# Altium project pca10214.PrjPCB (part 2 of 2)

## Sheet pca10214_sheet7_connectors.SchDoc: =BoardTitle+' - Connectors'
size A3; Organization: Nordic Semiconductor; DocumentNumber: 7; Revision: 0.3.1; SheetNumber: 7; SheetTotal: 8; Author: KJP; CompanyName: Nordic Semiconductor; DrawnBy: KJP; DocumentSize: A4
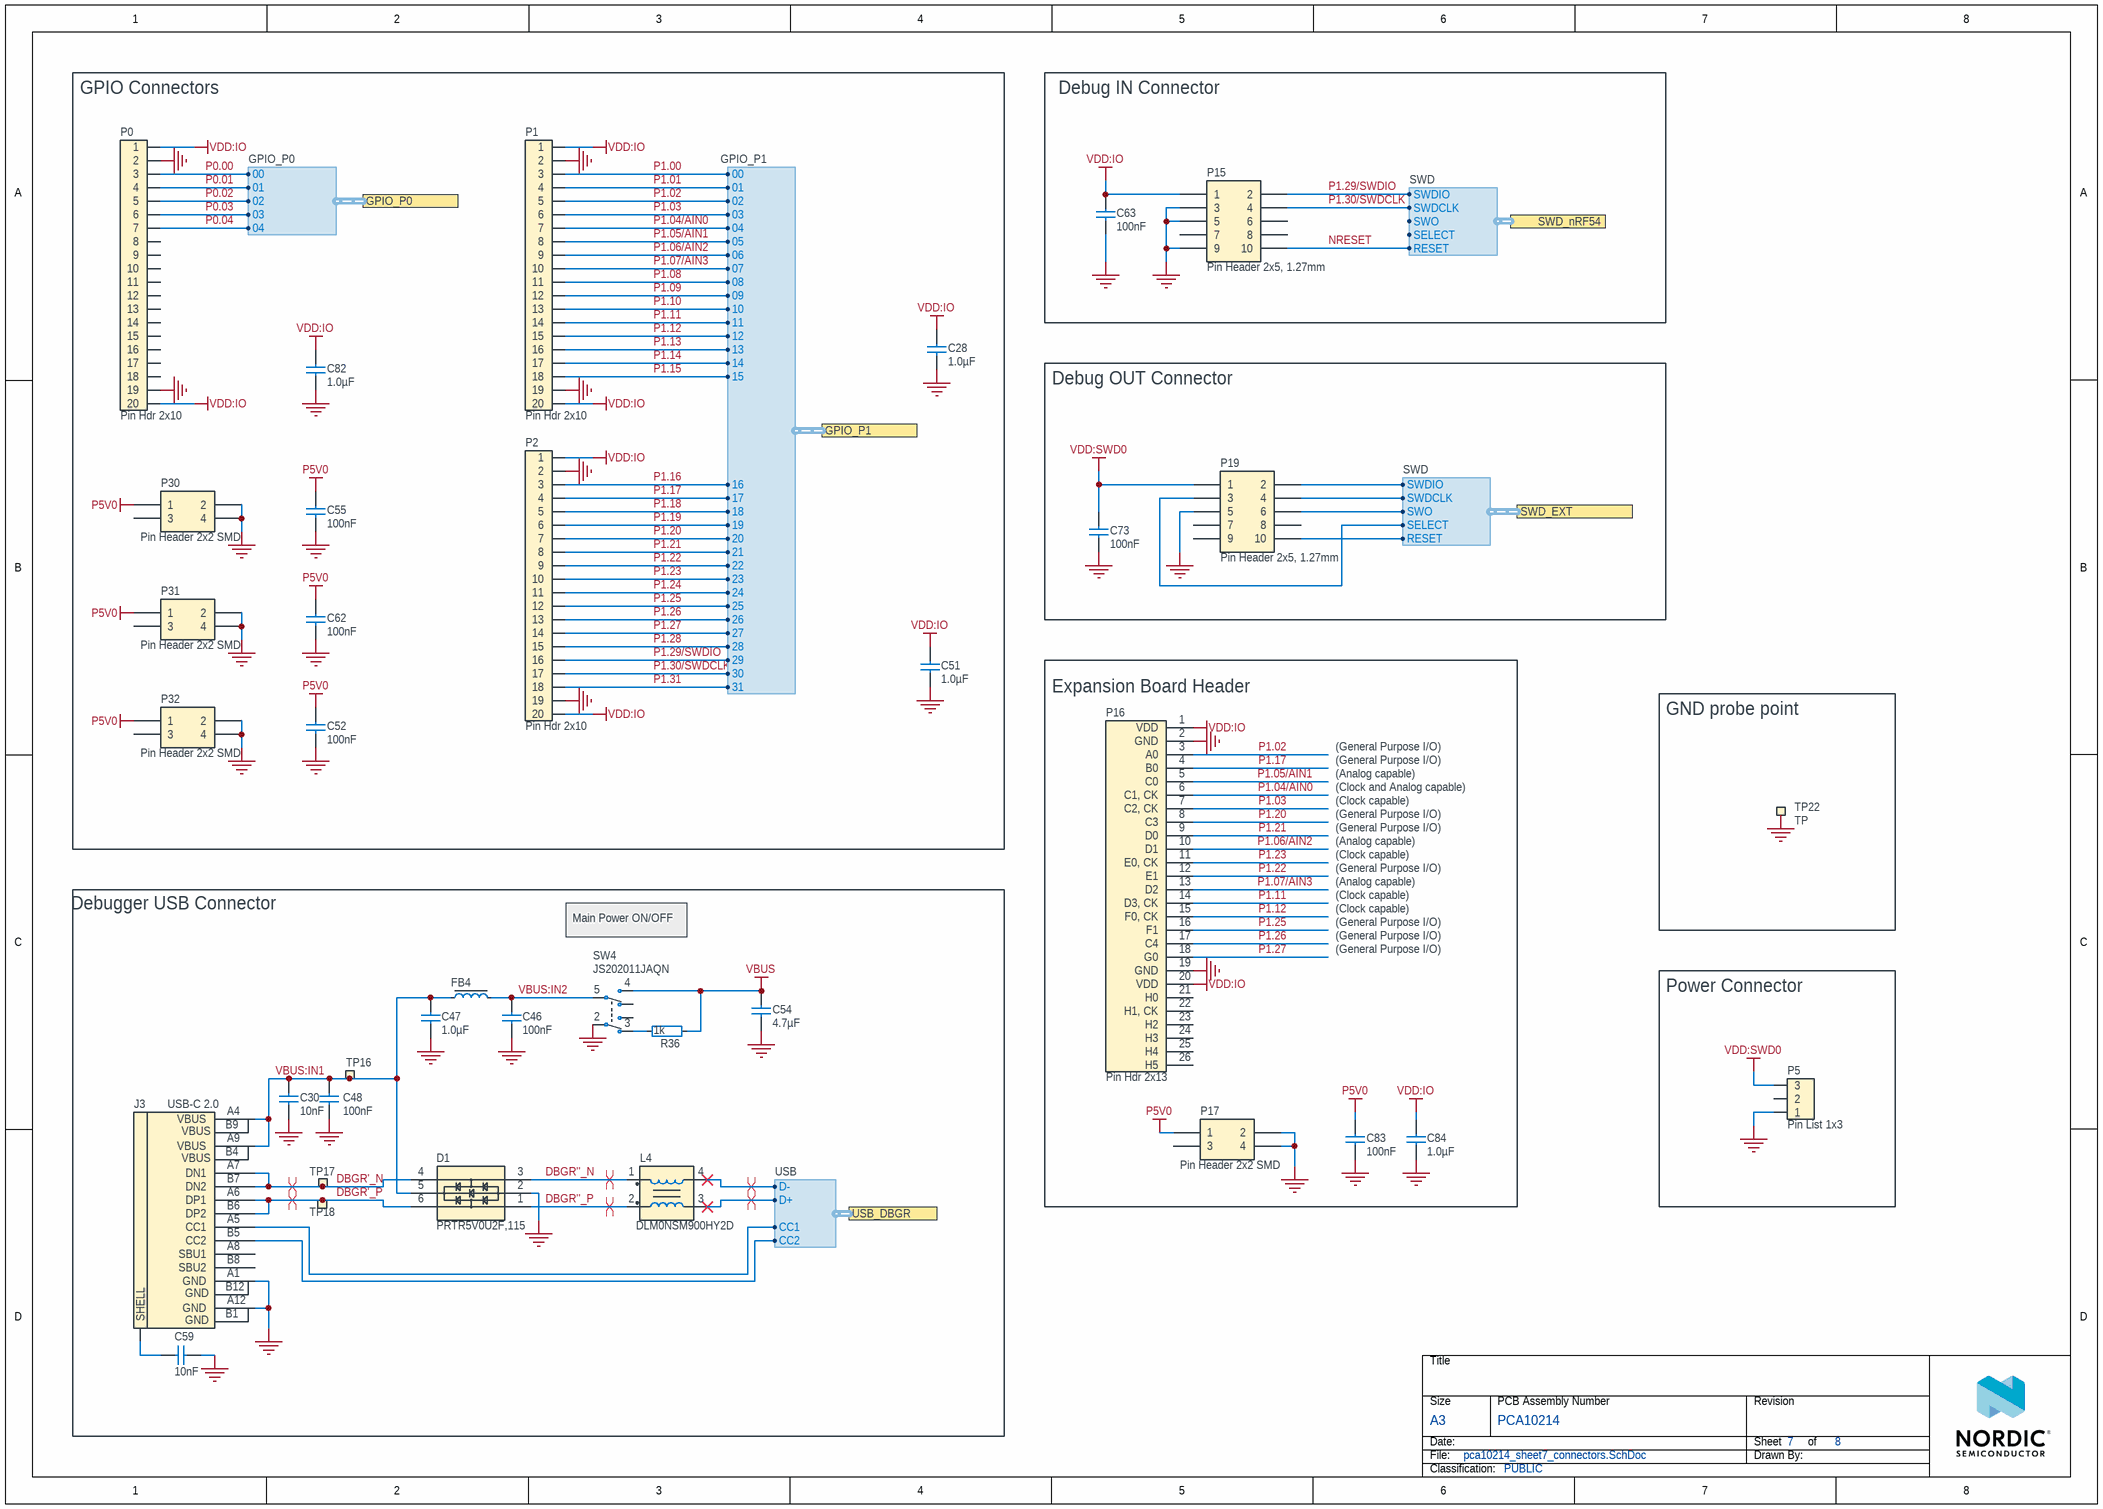
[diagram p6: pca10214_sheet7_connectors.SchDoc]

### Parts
C28  1.0µF  [CAPC1005X04L]
C30  10nF  [CAPC0603X03L_C]
C46  100nF  [CAPC0603X03L_C]
C47  1.0µF  [CAPC1005X04L]
C48  100nF  [CAPC0603X03L_C]
C51  1.0µF  [CAPC1005X04L]
C52  100nF  [CAPC0603X03L_C]
C54  4.7µF  [CAPC1608X06L]
C55  100nF  [CAPC0603X03L_C]
C59  10nF  [CAPC1608X06L]
C62  100nF  [CAPC0603X03L_C]
C63  100nF  [CAPC0603X03L_C]
C73  100nF  [CAPC0603X03L_C]
C82  1.0µF  [CAPC1005X04L]
C83  100nF  [CAPC0603X03L_C]
C84  1.0µF  [CAPC1005X04L]
D1  PRTR5V0U2F,115  [SON50P100X50-6N]
FB4  120R/0.55A  [INDC1005X04L]  (value not drawn)
J3  USB-C 2.0  [SD-80259-001]
L4  DLM0NSM900HY2D  [CMC0806X05N]
P0  Pin Hdr 2x10  [HDR_2x10-SMD]
P1  Pin Hdr 2x10  [HDR_2x10-SMD]
P2  Pin Hdr 2x10  [HDR_2x10-SMD]
P5  Pin List 1x3  [LIST_1x3_SMD]
P15  Pin Header 2x5, 1.27mm  [HDR_2x5-SMD-1.27mm-K]
P16  Pin Hdr 2x13  [HDR_2x13-SMD]
P17  Pin Header 2x2 SMD  [HDR_2x2-SMD]
P19  Pin Header 2x5, 1.27mm  [HDR_2x5-SMD-1.27mm-K]
P30  Pin Header 2x2 SMD  [HDR_2x2-SMD]
P31  Pin Header 2x2 SMD  [HDR_2x2-SMD]
P32  Pin Header 2x2 SMD  [HDR_2x2-SMD]
R36  1k  [RESC0603X03L_C]
SW4  Manufacturer Part Number: JS202011JAQN  [JS102011JAQN]  (hidden comment: Switch)
TP16  Ø1.5mm,SMD  [TP_SMD_D1.5mm]  (value not drawn)  (no BOM)
TP17  Ø1.5mm,SMD  [TP_SMD_D1.5mm]  (value not drawn)  (no BOM)
TP18  Ø1.5mm,SMD  [TP_SMD_D1.5mm]  (value not drawn)  (no BOM)
TP22  TP  [S1751]

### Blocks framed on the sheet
GPIO Connectors: C28 C51 C52 C55 C62 C82 P0-P2 P30-P32
Debug IN Connector: C63 P15
Debug OUT Connector: C73 P19
Expansion Board Header: C83 C84 P16 P17
GND probe point: TP22
Debugger USB Connector: C30 C46-C48 C54 C59 D1 FB4 J3 L4 R36 SW4 TP16-TP18
Power Connector: P5

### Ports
GPIO_P0 (harness GPIO_P0), GPIO_P1 (harness GPIO_P1), SWD_EXT (harness SWD), SWD_nRF54 (harness SWD), USB_DBGR (harness USB)

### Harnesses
USB: D+, D-, CC1, CC2
SWD: SWDIO, SWDCLK, SWO, RESET, SELECT
GPIO_P0: 02, 03, 04, 00, 01
GPIO_P1: 02, 03, 04, 00, 01, 05, 06, 07, 08, 09, 10, 11, 12, 13, 14, 15, 16, 17, 18, 19, 20, 21, 22, 23, 24, 25, 26, 27, 28, 29, 30, 31

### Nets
GND: C28.1 C30.2 C46.1 C47.1 C48.1 C51.1 C52.1 C54.2 C55.1 C59.2 C62.1 C63.1 C73.1 C82.1 C83.1 C84.1 D1.2(GND) J3.A1(GND) J3.A12(GND) P0.2 P0.19 P1.2 P1.19 P2.2 P2.19 P5.1 P15.3 P15.5 P15.9 P16.2(GND) P16.19(GND) P17.2 P17.4 P19.5 P30.2 P30.4 P31.2 P31.4 P32.2 P32.4 SW4.2(COM-1) TP22.1
P5V0: C52.2 C55.2 C62.2 C83.2 P17.1 P30.1 P31.1 P32.1
VBUS: C54.1 R36.2 SW4.4(N.O-2)
VDD:IO: C28.2 C51.2 C63.2 C82.2 C84.2 P0.1 P0.20 P1.1 P1.20 P2.1 P2.20 P15.1 P16.1(VDD) P16.20(VDD)
VDD:SWD0: C73.2 P5.3 P19.1
DBGR''_N: D1.3(IO2) L4.1
DBGR''_P: D1.1(IO1) L4.2
DBGR'_N: D1.4(IO2) J3.A7(DN1) J3.B7(DN2) TP17.1
DBGR'_P: D1.6(IO1) J3.A6(DP1) J3.B6(DP2) TP18.1
DBGR_N: L4.4 ; port USB_DBGR.D-
DBGR_P: L4.3 ; port USB_DBGR.D+
NRESET: P15.10 ; port SWD_nRF54.RESET
P0.00: P0.3 ; port GPIO_P0.00
P0.01: P0.4 ; port GPIO_P0.01
P0.02: P0.5 ; port GPIO_P0.02
P0.03: P0.6 ; port GPIO_P0.03
P0.04: P0.7 ; port GPIO_P0.04
P1.00: P1.3 ; port GPIO_P1.00
P1.01: P1.4 ; port GPIO_P1.01
P1.02: P1.5 P16.3(A0) ; port GPIO_P1.02
P1.03: P1.6 P16.7(C2,_CK) ; port GPIO_P1.03
P1.04/AIN0: P1.7 P16.6(C1,_CK) ; port GPIO_P1.04
P1.05/AIN1: P1.8 P16.5(C0) ; port GPIO_P1.05
P1.06/AIN2: P1.9 P16.10(D1) ; port GPIO_P1.06
P1.07/AIN3: P1.10 P16.13(D2) ; port GPIO_P1.07
P1.08: P1.11 ; port GPIO_P1.08
P1.09: P1.12 ; port GPIO_P1.09
P1.10: P1.13 ; port GPIO_P1.10
P1.11: P1.14 P16.14(D3,_CK) ; port GPIO_P1.11
P1.12: P1.15 P16.15(F0,_CK) ; port GPIO_P1.12
P1.13: P1.16 ; port GPIO_P1.13
P1.14: P1.17 ; port GPIO_P1.14
P1.15: P1.18 ; port GPIO_P1.15
P1.16: P2.3 ; port GPIO_P1.16
P1.17: P2.4 P16.4(B0) ; port GPIO_P1.17
P1.18: P2.5 ; port GPIO_P1.18
P1.19: P2.6 ; port GPIO_P1.19
P1.20: P2.7 P16.8(C3) ; port GPIO_P1.20
P1.21: P2.8 P16.9(D0) ; port GPIO_P1.21
P1.22: P2.9 P16.12(E1) ; port GPIO_P1.22
P1.23: P2.10 P16.11(E0,_CK) ; port GPIO_P1.23
P1.24: P2.11 ; port GPIO_P1.24
P1.25: P2.12 P16.16(F1) ; port GPIO_P1.25
P1.26: P2.13 P16.17(C4) ; port GPIO_P1.26
P1.27: P2.14 P16.18(G0) ; port GPIO_P1.27
P1.28: P2.15 ; port GPIO_P1.28
P1.29/SWDIO: P2.16 P15.2 ; port SWD_nRF54.SWDIO, port GPIO_P1.29
P1.30/SWDCLK: P2.17 P15.4 ; port SWD_nRF54.SWDCLK, port GPIO_P1.30
P1.31: P2.18 ; port GPIO_P1.31
SWD0_CLK_EXT: P19.4 ; port SWD_EXT.SWDCLK
SWD0_IO_EXT: P19.2 ; port SWD_EXT.SWDIO
SWD0_RESET_EXT: P19.10 ; port SWD_EXT.RESET
SWD0_SEL: P19.3 ; port SWD_EXT.SELECT
SWD0_SWO_EXT: P19.6 ; port SWD_EXT.SWO
VBUS:IN1: C30.1 C47.2 C48.2 D1.5(VCC) FB4.1 J3.A4(VBUS) J3.A9(VBUS) TP16.1
VBUS:IN2: C46.2 FB4.2 SW4.5(COM-2)
NetC59_1: C59.1 J3.SHLD(SHELL)
NetJ3_A5: J3.A5(CC1) ; port USB_DBGR.CC1
NetJ3_B5: J3.B5(CC2) ; port USB_DBGR.CC2
NetR36_1: R36.1 SW4.3(N.C-1)

Not connected (* = marked no-connect by the designer): J3 A8(SBU1) B8(SBU2); P0 8 9 10 11 12 13 14 15 16 17 18; P5 2; P15 6 7 8; P16 21(H0) 22(H1,_CK) 23(H2) 24(H3) 25(H4) 26(H5); P17 3; P19 7 8 9; P30 3; P31 3; P32 3; SW4 1(N.O-1) 6(N.C-2)

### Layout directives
differential pair; differential pair class DBGR; net class DBGR_USB: DBGR''_N, DBGR''_P, DBGR'_N, DBGR'_P, DBGR_N, DBGR_P

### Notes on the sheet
- (General Purpose I/O)
- (Analog capable)
- (Clock capable)
- (Clock and Analog capable)
- Main Power ON/OFF

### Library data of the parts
C28 C51 C82 C84 = C0402-1µ0-6.3V-X5R-10%: Capacitor, X5R, ±10%, 6.3V; Manufacturer: N.A.; Part number Norautron: 26207137; Part number NEMS: 100200498; Pad Count: 2; Component Status: Active
C30 = C0201-10n: Capacitor, X7R, ±10%; Manufacturer: N.A.; Part number IPS: 00000003480; Part number Norautron: 26621779; Part number NEMS: 100200067; Note: 10V; Pad Count: 2; Component Status: Active
C46 C48 C52 C55 C62 C63 C73 C83 = C0201-100n: Capacitor, X5R, ±10%; Manufacturer: N.A.; Part number IPS: 00000001248, 00000002505; Part number Norautron: 262071862; Part number NEMS: 100200078; Note: 16V; Pad Count: 2; Component Status: Active
C47 = C0402-1µ0-16V-X5R: Capacitor, Ceramic, X5R, ±10%, 16V; Manufacturer: Murata; Manufacturer Part Number: GRT155R61C105KE01D; Part number NEMS: 100200452; Component Status: Active; Pad Count: 2; Artikkelnr Noca: N.A.
C54 = C0603-4µ7-10V-X7S: Capacitor, X7S, ±10%, 10V; Manufacturer: N.A.; Part number IPS: 00000001779; Part number NEMS: 100200351; Pad Count: 2; Artikkelnr Noca: 20030013; Component Status: Active
C59 = C0603-10n-100V-X7R: Capacitor, X7R, ±10%, 100V; Manufacturer: Murata; Manufacturer Part Number: GCM188R72A103KA37D; Part number NEMS: 100200349; Component Status: Active; Pad Count: 2; Artikkelnr Noca: N.A.
D1 = PRTR5V0U2F,115: TVS DIODE 5.5VWM 6XSON; Manufacturer: Nexperia; Part number NEMS: 101300202; Component Status: Active; Pad Count: 6; Note: N.A.
FB4 = FB0402-120R@100M-500mA: Ferrite Bead, 120 Ohm @ 100MHz, 500mA, 250 mOhm Max; Manufacturer: Murata; Manufacturer Part Number: BLM15AG121SN1D; Part number IPS: 00000009954; Part number Norautron: 265230631; Part number NEMS: 100300099; Note: Chip EMIFIL Inductor Type Chip Ferrite Bead; Artikkelnr Noca: 33029317; Pad Count: 2; Component Status: Active
J3 = SD-80259-1021: USB-C Receptacle, 16 Pin, USB 2.0; Manufacturer: Bellweather Electronic Corp.; Part number NEMS: 100500830; Component Status: Active; Pad Count: 16; Note: N.A.; System: Connector
L4 = DLM0NSM900HY2D: 2 Line Common Mode Choke, 90Ohm @ 100MHz, Imax=100mA, DCR=4Ohm, VDC=5V,  -40°C ~ 85°C; Manufacturer: Murata Electronics; Part number NEMS: 100300513; Component Status: Active; Pad Count: 4; Note: N.A.
P0-P2 = Pin Header 2x10 SMD, 2.54mm: Pin Header 2x10, 2.54mm (100mil) SMD; Manufacturer: WCON; Manufacturer Part Number: 1125-1210S0M116CR09; Part number NEMS: 100500738; Pad Count: 20; Artikkelnr Noca: N.A.; Component Status: Active; System: Connector
P5 = Pin List 1x3 SMD: Pin List 1x3, 2.54mm (100mil), SMD; Manufacturer: WCON; Manufacturer Part Number: 1125-1103S0M116CR04; Part number Norautron: 26470016; Part number NEMS: 100500306; Note: N.A.; Pad Count: 3; Component Status: Active; System: Connector
P15 P19 = Pin Header 2x5 SMD, 1.27mm, KS: Pin Header 2x5, 1.27mm (50mil), SMD, Keying Shroud; Manufacturer: WCON; Manufacturer Part Number: 3132-10MS0BK00R5; Part number NEMS: 100500261; Note: (Replaced 3132-10MS0BK00R1); Artikkelnr Noca: N.A.; Pad Count: 10; Component Status: Active; System: Connector
P16 = Pin Header 2x13 SMD, 2.54mm: Pin Header 2x13, 2.54mm (100mil) SMD; Manufacturer: WCON; Manufacturer Part Number: 1125-1213S0M116CR09; Part number NEMS: 100500908; Component Status: Active; Pad Count: 26; Artikkelnr Noca: N.A.; System: Connector
P17 P30-P32 = Pin Header 2x2 SMD: Pin Header 2x2, SMD, 2.54mm (100mil); Manufacturer: WCON; Manufacturer Part Number: 1125-1202S0M116CR03; Part number NEMS: 100500770; Component Status: Active; Pad Count: 4; Note: N.A.; System: Connector
R36 = R0201-1k0: Resistor, ±1%, 0.05W; Manufacturer: N.A.; Part number IPS: 00000005786; Part number NEMS: 100100043; Component Status: Active; Pad Count: 2; Note: Chip Res 1%
SW4 = Switch-Slide-RA-J-Lead-DPDT-8.5x3.5mm_C&K: SMD slide Switch (ON-ON); Manufacturer: C&K; Part number IPS: 00000007811; Part number NEMS: 101500037; Component Status: Active; Pad Count: 6; Note: N.A.
TP16-TP18 = TP_SMD_Ø1.5MM: 1.5mm circular SMD testpad; Manufacturer: Nordic Semiconductor; Manufacturer Part Number: N.A.; Part number NEMS: 100500477; Pad Count: 1; Component Status: Active
TP22 = TP - S1751-46R: PC TEST POINT TIN SMD L; Manufacturer: Harwin; Part number NEMS: 100500525; Component Status: Active; Pad Count: 1; Note: N.A.

## Sheet pca10214_sheet8_mechanical.SchDoc: =BoardTitle+' - Mechanical'
size A4; Organization: Nordic Semiconductor; DocumentNumber: 89; Revision: 0.3.1; SheetNumber: 8; SheetTotal: 8; Author: KJP; CompanyName: Nordic Semiconductor; DrawnBy: KJP; DocumentSize: A4
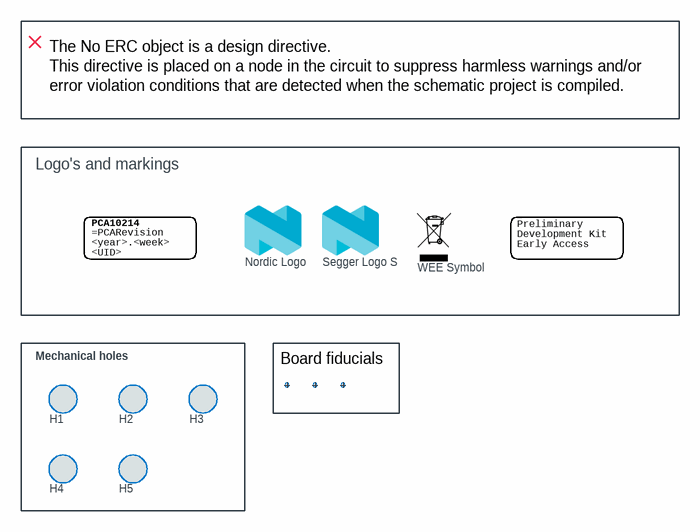
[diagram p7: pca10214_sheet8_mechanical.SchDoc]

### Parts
Fid1  Fiducial mark  [Fiducial]  (value not drawn)
Fid2  Fiducial mark  [Fiducial]  (value not drawn)
Fid3  Fiducial mark  [Fiducial]  (value not drawn)
H1  MountingHole_NPTH  [MountingHole_3.2_M3]  (value not drawn)  (no BOM)
H2  MountingHole_NPTH  [MountingHole_3.2_M3]  (value not drawn)  (no BOM)
H3  MountingHole_NPTH  [MountingHole_3.2_M3]  (value not drawn)  (no BOM)
H4  MountingHole_NPTH  [MountingHole_3.2_M3]  (value not drawn)  (no BOM)
H5  MountingHole_NPTH  [MountingHole_3.2_M3]  (value not drawn)  (no BOM)
LABEL1  12x12mm  [LabelSilk_12x12]  (value not drawn)
LABEL2  20x40mm  [LabelSilk_20x40]  (value not drawn)
LOGO1  Nordic Logo  [NORDIC_LOGO_LYING]  (no BOM)
LOGO2  Segger Logo S  [SEGGER_LOGO_S]  (no BOM)
LOGO3  WEE Symbol  [WEEE_3x4.5mm]  (no BOM)

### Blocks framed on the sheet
Logo's and markings: LABEL1 LABEL2 LOGO1-LOGO3
Mechanical holes: H1-H5

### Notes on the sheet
- The No ERC object is a design directive.
  This directive is placed on a node in the circuit to suppress harmless warnings and/or error violation conditions that are detected when the schematic project is compiled.
- Board fiducials

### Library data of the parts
Fid1-Fid3 = Fid-Mark: Manufacturer: N.A.; Part number NEMS: 100500073; Value: N.A.; Pad Count: 1; Component Status: Active; System: Connector
H1-H5 = MountingHole_3.2_M3: Mounting hole, 3.2mm, M3, no annular; Manufacturer: N.A.; Part number NEMS: 101200008; Rule: UNIONINDEX=0¦RULEKIND=Clearance¦NETSCOPE=DifferentNets¦LAYERKIND=SameLayer¦NAME=Schematic Clearance Constraint¦GAP=10mil¦GENERICCLEARANCE=10mil¦IGNOREPADTOPADCLEARANCEINFOOTPRINT=TRUE¦OBJECTCLEARANCES=ClearanceObj_Arc-ClearanceObj_Hole:0;ClearanceObj_Track-ClearanceObj_Hole:0;ClearanceObj_SMDPad-ClearanceObj_Hole:0;ClearanceObj_THPad-ClearanceObj_Hole:0;ClearanceObj_Via-ClearanceObj_Hole:0;ClearanceObj_Fill-ClearanceObj_Hole:0;ClearanceObj_Poly-ClearanceObj_Hole:0;ClearanceObj_Region-ClearanceObj_Hole:0;ClearanceObj_Text-ClearanceObj_Hole:0¦UNIT=Metric; Rule: UNIONINDEX=0¦RULEKIND=RoutingVias¦NETSCOPE=AnyNet¦LAYERKIND=SameLayer¦NAME=Schematic Routing Via Style¦HOLEWIDTH=0mil¦WIDTH=0mil¦VIASTYLE=Through Hole¦MINHOLEWIDTH=0mil¦MINWIDTH=0mil¦MAXHOLEWIDTH=78.7402mil¦MAXWIDTH=78.7402mil¦UNIT=Metric; Component Status: Active; Pad Count: 0
LABEL1 = Label_12x12: PCA version label, stick-on, 12x12mm; Manufacturer: Ellco Etikett; Manufacturer Part Number: A33512‐01; Part number NEMS: 101200028; Component Status: Active; Pad Count: 0; Note: N.A.
LABEL2 = Label_20x40: Early Access Label; Manufacturer: NA; Part number NEMS: 101200035; Component Status: Active; Pad Count: 0; Note: N.A.
LOGO1 = Nordic Logo lying: Manufacturer: N.A.; Part number NEMS: 101100001; Component Status: Active; Pad Count: 0
LOGO2 = Segger Logo S: Segger logo, small size; Manufacturer: N.A.; Part number NEMS: 101100004; Component Status: Active; Pad Count: 0
LOGO3 = WEEE Symbol 3x4.5mm: WEEE Directive symbol; Manufacturer: N.A.; Part number NEMS: 101100006; Component Status: Active; Pad Count: 0

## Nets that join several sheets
GND: pca10214_sheet2_nRF54LS05 (21 pins), pca10214_sheet3_debugger (33 pins), pca10214_sheet4_level_shifters (22 pins), pca10214_sheet5_misc (14 pins), pca10214_sheet6_power_supply (26 pins), pca10214_sheet7_connectors (42 pins)
P5V0: pca10214_sheet3_debugger (R40.2), pca10214_sheet6_power_supply (13 pins), pca10214_sheet7_connectors (8 pins)
VBUS: pca10214_sheet3_debugger (J4.5 R5.2), pca10214_sheet6_power_supply (C23.2 TP8.1 U10.21), pca10214_sheet7_connectors (C54.1 R36.2 SW4.4)
VDD:DBGR: pca10214_sheet3_debugger (29 pins), pca10214_sheet4_level_shifters (10 pins), pca10214_sheet6_power_supply (C29.1 U10.12)
VDD:IO: pca10214_sheet3_debugger (R41.2), pca10214_sheet4_level_shifters (7 pins), pca10214_sheet6_power_supply (R9.2 R37.2 TP11.1), pca10214_sheet7_connectors (14 pins)
VDD:nRF: pca10214_sheet2_nRF54LS05 (5 pins), pca10214_sheet4_level_shifters (R28.1), pca10214_sheet6_power_supply (P6.2 R24.1 R43.1)
VDD:SWD0: pca10214_sheet4_level_shifters (C14.1 R18.2 U7.11), pca10214_sheet7_connectors (C73.2 P5.3 P19.1)
DBGR_BUTTON: pca10214_sheet1_connections (SB2.2), pca10214_sheet3_debugger (U2.AL27)
DBGR_N: pca10214_sheet3_debugger (U2.B4), pca10214_sheet7_connectors (L4.4)
DBGR_P: pca10214_sheet3_debugger (U2.B2), pca10214_sheet7_connectors (L4.3)
LED_PWR_CTRL: pca10214_sheet3_debugger (U2.A17), pca10214_sheet6_power_supply (U10.8)
NetC64_2: pca10214_sheet5_misc (5 pins), pca10214_sheet6_power_supply (U10.31)
NetJ3_A5: pca10214_sheet6_power_supply (U10.23), pca10214_sheet7_connectors (J3.A5)
NetJ3_B5: pca10214_sheet6_power_supply (U10.24), pca10214_sheet7_connectors (J3.B5)
NetSB1_2: pca10214_sheet1_connections (SB1.2 SB2.1), pca10214_sheet5_misc (SW1.2)
NRESET: pca10214_sheet1_connections (SB1.1), pca10214_sheet2_nRF54LS05 (P3.1 P4.3 R1.2), pca10214_sheet4_level_shifters (U6.9), pca10214_sheet7_connectors (P15.10)
P0.00: pca10214_sheet2_nRF54LS05 (U1.23), pca10214_sheet5_misc (Q2.2 R10.1), pca10214_sheet7_connectors (P0.3)
P0.01: pca10214_sheet2_nRF54LS05 (U1.24), pca10214_sheet5_misc (Q3.2 R11.1), pca10214_sheet7_connectors (P0.4)
P0.02: pca10214_sheet2_nRF54LS05 (U1.27), pca10214_sheet5_misc (Q2.5 R12.1), pca10214_sheet7_connectors (P0.5)
P0.03: pca10214_sheet2_nRF54LS05 (U1.28), pca10214_sheet5_misc (Q3.5 R27.1), pca10214_sheet7_connectors (P0.6)
P0.04: pca10214_sheet2_nRF54LS05 (U1.29), pca10214_sheet5_misc (SW6.2), pca10214_sheet7_connectors (P0.7)
P1.00: pca10214_sheet2_nRF54LS05 (SB5.2), pca10214_sheet7_connectors (P1.3)
P1.01: pca10214_sheet2_nRF54LS05 (SB6.2), pca10214_sheet7_connectors (P1.4)
P1.02: pca10214_sheet2_nRF54LS05 (U1.3), pca10214_sheet7_connectors (P1.5 P16.3)
P1.03: pca10214_sheet2_nRF54LS05 (U1.4), pca10214_sheet7_connectors (P1.6 P16.7)
P1.04/AIN0: pca10214_sheet2_nRF54LS05 (U1.5), pca10214_sheet4_level_shifters (U5.6), pca10214_sheet7_connectors (P1.7 P16.6)
P1.05/AIN1: pca10214_sheet2_nRF54LS05 (U1.6), pca10214_sheet4_level_shifters (U5.3), pca10214_sheet7_connectors (P1.8 P16.5)
P1.06/AIN2: pca10214_sheet2_nRF54LS05 (U1.7), pca10214_sheet4_level_shifters (U5.13), pca10214_sheet7_connectors (P1.9 P16.10)
P1.07/AIN3: pca10214_sheet2_nRF54LS05 (U1.8), pca10214_sheet4_level_shifters (U5.9), pca10214_sheet7_connectors (P1.10 P16.13)
P1.08: pca10214_sheet2_nRF54LS05 (C41.2 U1.9), pca10214_sheet5_misc (SW5.2), pca10214_sheet7_connectors (P1.11)
P1.09: pca10214_sheet2_nRF54LS05 (U1.37), pca10214_sheet5_misc (SW3.2), pca10214_sheet7_connectors (P1.12)
P1.10: pca10214_sheet2_nRF54LS05 (U1.38), pca10214_sheet4_level_shifters (U4.6), pca10214_sheet7_connectors (P1.13)
P1.11: pca10214_sheet2_nRF54LS05 (U1.39), pca10214_sheet7_connectors (P1.14 P16.14)
P1.12: pca10214_sheet2_nRF54LS05 (U1.40), pca10214_sheet7_connectors (P1.15 P16.15)
P1.13: pca10214_sheet2_nRF54LS05 (U1.41), pca10214_sheet5_misc (SW2.2), pca10214_sheet7_connectors (P1.16)
P1.14: pca10214_sheet2_nRF54LS05 (U1.42), pca10214_sheet4_level_shifters (U4.3), pca10214_sheet7_connectors (P1.17)
P1.15: pca10214_sheet2_nRF54LS05 (U1.48), pca10214_sheet4_level_shifters (U4.13), pca10214_sheet7_connectors (P1.18)
P1.16: pca10214_sheet2_nRF54LS05 (U1.10), pca10214_sheet4_level_shifters (U4.9), pca10214_sheet7_connectors (P2.3)
P1.17: pca10214_sheet2_nRF54LS05 (U1.11), pca10214_sheet7_connectors (P2.4 P16.4)
P1.18: pca10214_sheet2_nRF54LS05 (U1.12), pca10214_sheet7_connectors (P2.5)
P1.19: pca10214_sheet2_nRF54LS05 (U1.13), pca10214_sheet7_connectors (P2.6)
P1.20: pca10214_sheet2_nRF54LS05 (U1.14), pca10214_sheet7_connectors (P2.7 P16.8)
P1.21: pca10214_sheet2_nRF54LS05 (U1.15), pca10214_sheet7_connectors (P2.8 P16.9)
P1.22: pca10214_sheet2_nRF54LS05 (U1.16), pca10214_sheet7_connectors (P2.9 P16.12)
P1.23: pca10214_sheet2_nRF54LS05 (U1.17), pca10214_sheet7_connectors (P2.10 P16.11)
P1.24: pca10214_sheet2_nRF54LS05 (U1.18), pca10214_sheet7_connectors (P2.11)
P1.25: pca10214_sheet2_nRF54LS05 (U1.19), pca10214_sheet7_connectors (P2.12 P16.16)
P1.26: pca10214_sheet2_nRF54LS05 (U1.20), pca10214_sheet7_connectors (P2.13 P16.17)
P1.27: pca10214_sheet2_nRF54LS05 (U1.21), pca10214_sheet7_connectors (P2.14 P16.18)
P1.28: pca10214_sheet2_nRF54LS05 (U1.22), pca10214_sheet7_connectors (P2.15)
P1.29/SWDIO: pca10214_sheet2_nRF54LS05 (U1.25), pca10214_sheet4_level_shifters (U6.6), pca10214_sheet7_connectors (P2.16 P15.2)
P1.30/SWDCLK: pca10214_sheet2_nRF54LS05 (U1.26), pca10214_sheet4_level_shifters (U6.3), pca10214_sheet7_connectors (P2.17 P15.4)
P1.31: pca10214_sheet2_nRF54LS05 (U1.36), pca10214_sheet7_connectors (P2.18)
SWD0_CLK: pca10214_sheet3_debugger (U2.B18), pca10214_sheet4_level_shifters (U7.4)
SWD0_CLK_EXT: pca10214_sheet4_level_shifters (U7.8), pca10214_sheet7_connectors (P19.4)
SWD0_IO: pca10214_sheet3_debugger (U2.B16), pca10214_sheet4_level_shifters (U7.5)
SWD0_IO_EXT: pca10214_sheet4_level_shifters (U7.7), pca10214_sheet7_connectors (P19.2)
SWD0_RESET: pca10214_sheet3_debugger (U2.B22), pca10214_sheet4_level_shifters (U7.2)
SWD0_RESET_EXT: pca10214_sheet4_level_shifters (U7.10), pca10214_sheet7_connectors (P19.10)
SWD0_SEL: pca10214_sheet3_debugger (U2.B24), pca10214_sheet4_level_shifters (Q1.5), pca10214_sheet7_connectors (P19.3)
SWD0_SWO: pca10214_sheet3_debugger (U2.B20), pca10214_sheet4_level_shifters (U7.3)
SWD0_SWO_EXT: pca10214_sheet4_level_shifters (U7.9), pca10214_sheet7_connectors (P19.6)
SWD3_CLK: pca10214_sheet3_debugger (U2.R1), pca10214_sheet4_level_shifters (U14.3)
SWD3_CTRL: pca10214_sheet3_debugger (U2.AB2), pca10214_sheet4_level_shifters (R31.2 U6.1 U6.4 U6.11)
SWD3_IO: pca10214_sheet3_debugger (U2.N1), pca10214_sheet4_level_shifters (U14.4)
SWD3_RESET: pca10214_sheet3_debugger (U2.AA1), pca10214_sheet4_level_shifters (U14.5)
TWI0_SCL: pca10214_sheet3_debugger (U2.AF2), pca10214_sheet6_power_supply (U10.14)
TWI0_SDA: pca10214_sheet3_debugger (U2.AE1), pca10214_sheet6_power_supply (U10.13)
UART0_CTRL: pca10214_sheet3_debugger (U2.R31), pca10214_sheet4_level_shifters (R14.2 U4.1 U4.4 U12.12)
UART0_CTS: pca10214_sheet3_debugger (R32.1 U2.AL9), pca10214_sheet4_level_shifters (U12.5)
UART0_HWFC: pca10214_sheet3_debugger (U2.AK16), pca10214_sheet4_level_shifters (R13.2 U4.11 U4.15)
UART0_RTS: pca10214_sheet3_debugger (U2.AL5), pca10214_sheet4_level_shifters (U12.4)
UART0_RxD: pca10214_sheet3_debugger (U2.AL19), pca10214_sheet4_level_shifters (U12.3)
UART0_TxD: pca10214_sheet3_debugger (U2.U31), pca10214_sheet4_level_shifters (U12.2)
UART1_CTRL: pca10214_sheet3_debugger (U2.AK18), pca10214_sheet4_level_shifters (R16.2 U5.1 U5.4 U13.12)
UART1_CTS: pca10214_sheet3_debugger (R56.1 U2.AL15), pca10214_sheet4_level_shifters (U13.5)
UART1_HWFC: pca10214_sheet3_debugger (U2.AK20), pca10214_sheet4_level_shifters (R15.2 U5.11 U5.15)
UART1_RTS: pca10214_sheet3_debugger (U2.AL13), pca10214_sheet4_level_shifters (U13.4)
UART1_RxD: pca10214_sheet3_debugger (U2.AL21), pca10214_sheet4_level_shifters (U13.3)
UART1_TxD: pca10214_sheet3_debugger (U2.AL23), pca10214_sheet4_level_shifters (U13.2)

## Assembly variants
Release: not fitted C2 C13 C16 C41 C56 C59 C67 P3 P4 P15 R24 R28 R30 R41 R42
